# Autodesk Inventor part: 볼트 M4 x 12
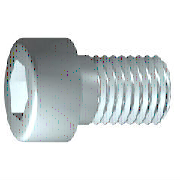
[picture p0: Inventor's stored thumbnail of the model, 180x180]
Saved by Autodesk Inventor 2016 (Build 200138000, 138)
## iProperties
IsCustomPart: 0
Created: 2012-02
Part Number: 볼트 M4 x 12
Material: 스테인리스강
Description: 6각 소켓 머리 캡 나사
Document SubType Name: Modeling
Standard: ISO 4762
Designer: mduedu
Standard Revision: Fourth edition 2004-03-01
Standards Organization: ISO
Language: ko-KR
Size Designation: M4 x 12
Categories: <MemberInstance><Categories><Category DisplayName="조임쇠" InternalName="e4da775c-781d-43d5-af7c-5136215cf5a6" Mnemonic="FSTN"><Category DisplayName="볼트" InternalN
Density: 8.08 g/cm^3
Appearance: 반광택
Author: mduedu
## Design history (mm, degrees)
sketch "스케치1"
  geometry: L1 (-1, 0)-(12, 0); L2 (12, 0)-(12, 2); L3 (12, 2)-(1.75, 2); L4 (1.75, 2)-(1.32, 2); L5 (1.32, 2)-(0, 2); L6 (0, 2)-(0, 3.5); L7 (0, 3.5)-(-4, 3.5); L8 (-4, 3.5)-(-4, 1.732); L9 (-4, 1.732)-(-2, 1.732); L10 (-2, 1.732)-(-1, 0); L11 (-7.2, 0)-(15.2, 0) reference; L12 (0, -0.7)-(0, 4.2) reference; L13 (1.75, 2)-(0, 2)
  constraints: 22 end point, 6 parallel, 2 collinear, 2 perpendicular, 1 horizontal, 1 point on line
  dimensions: "d1" = 10.25 distance from line of L3.end L2 (= GEL); "d2" = 0.42952 distance of L4.end L3.end (computed from GAL); "d3" = 4 distance between parallel lines of L8 L6 (= KOH); "d4" = 2 distance of L8.end L9.end (= INTI); "d5" = 60 deg angle of L10 L1; "d6" = 4 diameter of L3 L1 (= GD); "d7" = 4 diameter of L5 L1 (= BDM); "d8" = 3.4641 diameter of L9 L1 (= 1.1547 x SW); "d9" = 7 diameter of L7 L1 (= KOD); "d26" = 12 distance between parallel lines of L12 L2 (= NLG)
revolve "본체" sketch "스케치1" stored, may be unused: angle "d10" = 90 deg
sketch "스케치2"
  geometry: L1 (0, -4.9)-(0, 4.9) reference; L2 (-4.9, 0)-(4.9, 0) reference; L3 (1.732, 0)-(0.866, -1.5); L4 (0.866, -1.5)-(-0.866, -1.5); L5 (-0.866, -1.5)-(-1.732, 0); L6 (-1.732, 0)-(-0.866, 1.5); L7 (-0.866, 1.5)-(0.866, 1.5); L8 (0.866, 1.5)-(1.732, 0); 2 further points
  constraints: 12 end point, 1 coincident, 1 horizontal alignment, 1 point on line, 12 other
extrude "슬롯" join sketch "스케치2" stored distance "d11" = 10; taper "d12" = 0 deg
workplane "Work Plane1"
fillet "Fillet2" dims "d30" = 0.1 (= R)
body "Solid1"
fillet "모깎기1" dims "d17" = 0.4 (= RR)
feature "스레드" dims "d13" = 10.25 (= GEL), "d14" = 0
chamfer "모따기1" distance "d15" = 0.42941 (= -0.5 x SPD + 0.5 x GD); stored, may be unused: second distance "d16" = 0.42941 (= GUL), angle "d27" = 45 deg
other parameters: "GD" = 4 [user parameter; used in 2 equation terms], "NLG" = 12 [user parameter; used in 1 equation term], "GEL" = 10.25 [user parameter; used in 2 equation terms], "KOD" = 7 [user parameter; used in 1 equation term], "KOH" = 4 [user parameter; used in 1 equation term], "INTI" = 2 [user parameter; used in 1 equation term], "GAL" = 0.42941 (= 0.61345 x PTC) [user parameter; used in 1 equation term], "GUL" = 0.42941 (= 0.61345 x PTC) [user parameter; used in 1 equation term], "BDM" = 4 (= NND) [user parameter; used in 1 equation term], "SW" = 3 [user parameter; used in 2 equation terms], "RR" = 0.4 [user parameter; used in 1 equation term], "SPD" = 3.14117 (= NND - 1.2269 x PTC) [user parameter; used in 1 equation term], "d19" = 0, "d28" = 0, "d29" = 0, "R" = 0.1 [user parameter; used in 1 equation term], "TOA" = 30 deg [user parameter], "GD1" = 3.14117 (= THREADDIA - 1.2269 x PTC) [user parameter], "THREADDIA" = 4 [user parameter; used in 1 equation term], "FAWI" = 45 deg [user parameter], "TPU" = 14.28571 (computed from PTC) [user parameter], "PTC" = 0.7 [user parameter; used in 5 equation terms], "NND" = 4 [user parameter; used in 2 equation terms], "E0" = 3.465 (= 1.155 x SW) [user parameter]
